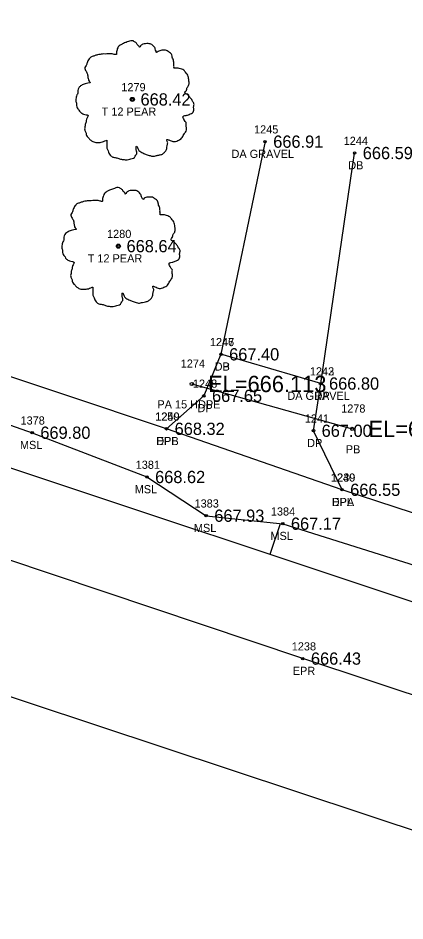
# Model space of a CAD drawing. Extents: x 1655137 to 1657928, y 1003994 to 1005407.
# Drawn here: x 1656148.5 to 1656195.9, y 1004645.1 to 1004755.9 of the extents above; entities that cross this region are included whole.
import ezdxf

# ---------------------------------------------------------------- set-up
doc = ezdxf.new("R2010")
doc.units = 0
for name, color, linetype in [('RD_EX_DR_Pipe', 7, 'Continuous'), ('RD_EX_DR_Pipe_txCode', 7, 'Continuous'), ('RD_EX_Driveway', 7, 'Continuous'), ('RD_EX_Driveway_txCode', 7, 'Continuous'), ('RD_EX_Fence_Other', 7, 'Continuous'), ('RD_EX_Misc', 7, 'Continuous'), ('RD_EX_Misc_txCode', 7, 'Continuous'), ('RD_EX_Road', 7, 'Continuous'), ('RD_EX_Road_txCode', 7, 'Continuous'), ('RD_EX_TX_Driveway_ELEV', 7, 'Continuous'), ('RD_EX_TX_Misc_ELEV', 7, 'Continuous'), ('RD_EX_TX_Road_ELEV', 7, 'Continuous'), ('RD_EX_TX_VEG_ELEV', 7, 'Continuous'), ('RD_EX_VEG', 7, 'Continuous'), ('RD_EX_VEG_txCode', 7, 'Continuous'), ('RD_HC_Cl', 7, 'Continuous'), ('RD_HC_Data_Tic', 7, 'Continuous'), ('RD_SMD_Locator', 7, 'Continuous'), ('RD_TX_Pipe_ElevEX', 7, 'Continuous')]:
    doc.layers.add(name, color=color, linetype=linetype)

msp = doc.modelspace()

# ---------------------------------------------------------------- linework, layer by layer
at = {"layer": 'RD_EX_DR_Pipe'}
msp.add_line((1656169.82, 1004711.01), (1656189.47, 1004705.5), dxfattribs=at)
at = {"layer": 'RD_EX_Driveway'}
for p, q in [((1656178.8, 1004740.74), (1656173.4, 1004714.65)), ((1656185.64, 1004711.06), (1656189.77, 1004739.34))]:
    msp.add_line(p, q, dxfattribs=at)
msp.add_lwpolyline([(1656188.23, 1004698.03), (1656184.73, 1004705.27), (1656185.64, 1004711.06), (1656173.4, 1004714.65), (1656171.3, 1004709.55), (1656166.72, 1004705.51)], dxfattribs=at)
at = {"layer": 'RD_EX_Fence_Other'}
msp.add_lwpolyline([(1656052.39, 1004677.71), (1656061.84, 1004701.05), (1656117.12, 1004682.78), (1656207.41, 1004652.79), (1656216.44, 1004637.08), (1656207.49, 1004611.28)], dxfattribs=at)
at = {"layer": 'RD_EX_Misc'}
msp.add_lwpolyline([(1655875.57, 1004783.81), (1655899.12, 1004775.73), (1655924.14, 1004767.92), (1655957.49, 1004756.44), (1655982.24, 1004748.48), (1656011.78, 1004739.5), (1656033.16, 1004732.17), (1656057.84, 1004724.63), (1656091.05, 1004714.31), (1656106.3, 1004710.84), (1656119.06, 1004707.85), (1656127.53, 1004711.03), (1656137.41, 1004709.54), (1656150.27, 1004705.03), (1656164.33, 1004699.6), (1656171.58, 1004694.85), (1656180.97, 1004693.87), (1656197.98, 1004688.49), (1656215.11, 1004682.58), (1656240.68, 1004675.39), (1656271.88, 1004665.01), (1656304.44, 1004655.08)], dxfattribs=at)
at = {"layer": 'RD_EX_Road'}
for points in [[(1656365.12, 1004639.99), (1656336.04, 1004649.34), (1656302.55, 1004660.37), (1656279.15, 1004668.23), (1656240.07, 1004681.05), (1656188.23, 1004698.03), (1656166.72, 1004705.51), (1656141.16, 1004714.06), (1656093.11, 1004730.11), (1656044.16, 1004746.75), (1655996.36, 1004762.45), (1655947.2, 1004778.68), (1655899.09, 1004794.03), (1655850.62, 1004809.99), (1655801.91, 1004826.1), (1655753.09, 1004842.31), (1655704.25, 1004858.1)], [(1656358.5, 1004619.83), (1656328.78, 1004629.48), (1656280.77, 1004645.39), (1656247.66, 1004656.11), (1656244.5, 1004656.52), (1656222.03, 1004663.57), (1656217.65, 1004665.96), (1656183.42, 1004677.32), (1656134.59, 1004693.72), (1656086.19, 1004709.75), (1656037.58, 1004726.13), (1655989.57, 1004741.99), (1655940.62, 1004757.88), (1655892.37, 1004773.61), (1655843.48, 1004789.36), (1655805.73, 1004801.4), (1655779.22, 1004810.43), (1655768.8, 1004813.1), (1655744.59, 1004822.13), (1655698.83, 1004837.65)]]:
    msp.add_lwpolyline(points, dxfattribs=at)
at = {"layer": 'RD_EX_VEG'}
msp.add_lwpolyline([(1656061.84, 1004701.05), (1656117.12, 1004682.78), (1656207.41, 1004652.79)], dxfattribs=at)
for centre, radius in [((1656162.54, 1004745.92), 0.25), ((1656162.53, 1004745.91), 0.0001), ((1656160.83, 1004727.92), 0.25), ((1656160.82, 1004727.9), 0.0001)]:
    msp.add_circle(centre, radius, dxfattribs=at)
for points in [[(1656162.67, 1004753.09), (1656162.37, 1004753.12), (1656162.05, 1004753.02), (1656161.8, 1004752.92), (1656161.57, 1004752.84), (1656161.35, 1004752.74), (1656161.05, 1004752.57), (1656160.82, 1004752.37), (1656160.7, 1004752.12), (1656160.65, 1004751.89), (1656160.6, 1004751.62), (1656160.6, 1004751.44), (1656160.47, 1004751.42), (1656160.32, 1004751.44), (1656160.07, 1004751.52), (1656159.82, 1004751.52), (1656159.57, 1004751.52), (1656159.22, 1004751.49), (1656158.87, 1004751.49), (1656158.6, 1004751.44), (1656158.27, 1004751.39), (1656157.9, 1004751.27), (1656157.55, 1004751.14), (1656157.25, 1004750.89), (1656157, 1004750.42), (1656156.87, 1004750.07), (1656156.72, 1004749.82), (1656156.87, 1004749.37), (1656157.05, 1004749.02), (1656157.07, 1004748.82), (1656157.15, 1004748.39), (1656157.25, 1004748.17), (1656157.37, 1004747.97), (1656157.3, 1004747.94), (1656156.92, 1004747.89), (1656156.62, 1004747.79), (1656156.2, 1004747.57), (1656155.97, 1004747.34), (1656155.87, 1004747.02), (1656155.85, 1004746.67), (1656155.75, 1004746.47), (1656155.67, 1004746.19), (1656155.65, 1004746.12), (1656155.6, 1004745.79), (1656155.7, 1004745.34), (1656155.72, 1004745), (1656155.85, 1004744.77), (1656156, 1004744.6), (1656156.17, 1004744.35), (1656156.57, 1004744.12), (1656156.9, 1004744.02), (1656157.1, 1004744), (1656156.92, 1004743.5), (1656156.87, 1004743.15), (1656156.75, 1004742.75), (1656156.75, 1004742.67), (1656156.7, 1004742.2), (1656156.85, 1004741.87), (1656156.92, 1004741.5), (1656157.1, 1004741.27), (1656157.37, 1004740.97), (1656157.7, 1004740.75), (1656158.2, 1004740.62), (1656158.6, 1004740.65), (1656159.17, 1004740.82), (1656159.42, 1004740.9), (1656159.4, 1004740.72), (1656159.42, 1004740.35), (1656159.42, 1004739.92), (1656159.57, 1004739.6), (1656159.67, 1004739.32), (1656159.82, 1004739.07), (1656160.15, 1004738.85), (1656160.55, 1004738.77), (1656160.97, 1004738.62), (1656161.42, 1004738.55), (1656161.92, 1004738.52), (1656162.52, 1004738.67), (1656162.8, 1004738.8), (1656162.9, 1004738.97), (1656163.1, 1004739.35), (1656163.05, 1004739.57), (1656163.07, 1004740.17), (1656163.17, 1004740), (1656163.35, 1004739.65), (1656163.84, 1004739.35), (1656164.24, 1004739.17), (1656164.72, 1004739.02), (1656165.02, 1004738.95), (1656165.49, 1004739.02), (1656165.87, 1004739.1), (1656166.24, 1004739.22), (1656166.54, 1004739.5), (1656166.72, 1004739.77), (1656166.77, 1004740.05), (1656166.84, 1004740.42), (1656166.89, 1004740.6)], [(1656166.89, 1004740.6), (1656166.82, 1004740.77), (1656166.77, 1004741.02), (1656166.84, 1004741), (1656167.02, 1004740.95), (1656167.29, 1004740.82), (1656167.52, 1004740.75), (1656167.84, 1004740.77), (1656168.12, 1004740.87), (1656168.57, 1004741.15), (1656168.84, 1004741.62), (1656169.12, 1004742.02), (1656169.19, 1004742.35), (1656169.14, 1004742.57), (1656169.12, 1004743.07), (1656168.92, 1004743.32), (1656168.87, 1004743.45), (1656168.77, 1004743.85), (1656168.84, 1004743.9), (1656169.12, 1004743.95), (1656169.49, 1004744.07), (1656169.77, 1004744.2), (1656169.99, 1004744.37), (1656170.07, 1004744.6), (1656170.04, 1004745), (1656170.09, 1004745.39), (1656170.02, 1004745.54), (1656169.92, 1004745.69), (1656169.84, 1004745.89), (1656169.69, 1004746.04), (1656169.59, 1004746.19), (1656169.49, 1004746.29), (1656169.37, 1004746.44), (1656169.19, 1004746.57), (1656169.04, 1004746.62), (1656168.99, 1004746.77), (1656169.14, 1004746.97), (1656169.19, 1004747.07), (1656169.22, 1004747.29), (1656169.44, 1004747.64), (1656169.49, 1004748.04), (1656169.44, 1004748.47), (1656169.39, 1004748.74), (1656169.24, 1004749.02), (1656169.04, 1004749.27), (1656168.92, 1004749.44), (1656168.74, 1004749.57), (1656168.42, 1004749.69), (1656168.17, 1004749.74), (1656167.82, 1004749.74), (1656167.62, 1004749.79), (1656167.64, 1004749.84), (1656167.64, 1004749.99), (1656167.64, 1004750.27), (1656167.57, 1004750.72), (1656167.42, 1004751.22), (1656167.42, 1004751.24), (1656167.32, 1004751.49), (1656167.09, 1004751.69), (1656166.92, 1004751.79), (1656166.72, 1004751.92), (1656166.47, 1004751.94), (1656166.17, 1004751.94), (1656165.89, 1004751.89), (1656165.69, 1004751.79), (1656165.52, 1004751.67), (1656165.44, 1004751.82), (1656165.34, 1004752.12), (1656165.29, 1004752.27), (1656165.14, 1004752.44), (1656164.92, 1004752.64), (1656164.47, 1004752.77), (1656163.84, 1004752.69), (1656163.55, 1004752.49), (1656163.4, 1004752.32), (1656163.35, 1004752.44), (1656163.15, 1004752.64), (1656163.05, 1004752.82), (1656162.87, 1004752.94), (1656162.72, 1004753.04), (1656162.62, 1004753.09)], [(1656160.96, 1004735.09), (1656160.66, 1004735.11), (1656160.34, 1004735.01), (1656160.09, 1004734.91), (1656159.86, 1004734.84), (1656159.64, 1004734.74), (1656159.34, 1004734.56), (1656159.11, 1004734.36), (1656158.99, 1004734.11), (1656158.94, 1004733.89), (1656158.89, 1004733.61), (1656158.89, 1004733.44), (1656158.76, 1004733.41), (1656158.61, 1004733.44), (1656158.36, 1004733.51), (1656158.11, 1004733.51), (1656157.86, 1004733.51), (1656157.51, 1004733.49), (1656157.16, 1004733.49), (1656156.89, 1004733.44), (1656156.56, 1004733.39), (1656156.19, 1004733.26), (1656155.84, 1004733.14), (1656155.54, 1004732.89), (1656155.29, 1004732.41), (1656155.16, 1004732.06), (1656155.01, 1004731.81), (1656155.16, 1004731.36), (1656155.34, 1004731.01), (1656155.36, 1004730.81), (1656155.44, 1004730.39), (1656155.54, 1004730.16), (1656155.66, 1004729.96), (1656155.59, 1004729.94), (1656155.21, 1004729.89), (1656154.91, 1004729.79), (1656154.49, 1004729.56), (1656154.26, 1004729.34), (1656154.16, 1004729.01), (1656154.14, 1004728.66), (1656154.04, 1004728.46), (1656153.96, 1004728.19), (1656153.94, 1004728.11), (1656153.89, 1004727.79), (1656153.99, 1004727.34), (1656154.01, 1004726.99), (1656154.14, 1004726.77), (1656154.29, 1004726.59), (1656154.46, 1004726.34), (1656154.86, 1004726.12), (1656155.19, 1004726.02), (1656155.39, 1004725.99), (1656155.21, 1004725.49), (1656155.16, 1004725.14), (1656155.04, 1004724.74), (1656155.04, 1004724.67), (1656154.99, 1004724.19), (1656155.14, 1004723.87), (1656155.21, 1004723.49), (1656155.39, 1004723.27), (1656155.66, 1004722.97), (1656155.99, 1004722.74), (1656156.49, 1004722.62), (1656156.89, 1004722.64), (1656157.46, 1004722.82), (1656157.71, 1004722.89), (1656157.69, 1004722.72), (1656157.71, 1004722.34), (1656157.71, 1004721.92), (1656157.86, 1004721.59), (1656157.96, 1004721.32), (1656158.11, 1004721.07), (1656158.44, 1004720.84), (1656158.84, 1004720.77), (1656159.26, 1004720.62), (1656159.71, 1004720.54), (1656160.21, 1004720.52), (1656160.81, 1004720.67), (1656161.08, 1004720.79), (1656161.18, 1004720.97), (1656161.38, 1004721.34), (1656161.33, 1004721.57), (1656161.36, 1004722.17), (1656161.46, 1004721.99), (1656161.63, 1004721.64), (1656162.13, 1004721.34), (1656162.53, 1004721.17), (1656163.01, 1004721.02), (1656163.31, 1004720.94), (1656163.78, 1004721.02), (1656164.16, 1004721.09), (1656164.53, 1004721.22), (1656164.83, 1004721.49), (1656165.01, 1004721.77), (1656165.06, 1004722.04), (1656165.13, 1004722.42), (1656165.18, 1004722.59)], [(1656165.18, 1004722.59), (1656165.11, 1004722.77), (1656165.06, 1004723.02), (1656165.13, 1004722.99), (1656165.31, 1004722.94), (1656165.58, 1004722.82), (1656165.81, 1004722.74), (1656166.13, 1004722.77), (1656166.41, 1004722.87), (1656166.86, 1004723.14), (1656167.13, 1004723.62), (1656167.41, 1004724.02), (1656167.48, 1004724.34), (1656167.43, 1004724.57), (1656167.41, 1004725.07), (1656167.21, 1004725.32), (1656167.16, 1004725.44), (1656167.06, 1004725.84), (1656167.13, 1004725.89), (1656167.41, 1004725.94), (1656167.78, 1004726.07), (1656168.06, 1004726.19), (1656168.28, 1004726.37), (1656168.36, 1004726.59), (1656168.33, 1004726.99), (1656168.38, 1004727.39), (1656168.31, 1004727.54), (1656168.21, 1004727.69), (1656168.13, 1004727.89), (1656167.98, 1004728.04), (1656167.88, 1004728.19), (1656167.78, 1004728.29), (1656167.66, 1004728.44), (1656167.48, 1004728.56), (1656167.33, 1004728.61), (1656167.28, 1004728.76), (1656167.43, 1004728.96), (1656167.48, 1004729.06), (1656167.51, 1004729.29), (1656167.73, 1004729.64), (1656167.78, 1004730.04), (1656167.73, 1004730.46), (1656167.68, 1004730.74), (1656167.53, 1004731.01), (1656167.33, 1004731.26), (1656167.21, 1004731.44), (1656167.03, 1004731.56), (1656166.71, 1004731.69), (1656166.46, 1004731.74), (1656166.11, 1004731.74), (1656165.91, 1004731.79), (1656165.93, 1004731.84), (1656165.93, 1004731.99), (1656165.93, 1004732.26), (1656165.86, 1004732.71), (1656165.71, 1004733.21), (1656165.71, 1004733.24), (1656165.61, 1004733.49), (1656165.38, 1004733.69), (1656165.21, 1004733.79), (1656165.01, 1004733.91), (1656164.76, 1004733.94), (1656164.46, 1004733.94), (1656164.18, 1004733.89), (1656163.98, 1004733.79), (1656163.81, 1004733.66), (1656163.73, 1004733.81), (1656163.63, 1004734.11), (1656163.58, 1004734.26), (1656163.43, 1004734.44), (1656163.21, 1004734.64), (1656162.76, 1004734.76), (1656162.13, 1004734.69), (1656161.83, 1004734.49), (1656161.68, 1004734.31), (1656161.63, 1004734.44), (1656161.43, 1004734.64), (1656161.33, 1004734.81), (1656161.16, 1004734.94), (1656161.01, 1004735.04), (1656160.91, 1004735.09)]]:
    msp.add_spline(points, degree=3, dxfattribs=at)
at = {"layer": 'RD_HC_Cl'}
msp.add_line((1656069.26, 1004726.84), (1656507.36, 1004580.77), dxfattribs=at)
at = {"layer": 'RD_HC_Data_Tic'}
msp.add_line((1656179.44, 1004690.11), (1656180.7, 1004693.9), dxfattribs=at)
at = {"layer": 'RD_SMD_Locator'}
for centre, radius in [((1656162.54, 1004745.92), 0.15), ((1656178.8, 1004740.74), 0.15), ((1656189.77, 1004739.34), 0.15), ((1656160.83, 1004727.92), 0.15), ((1656173.4, 1004714.65), 0.15), ((1656173.4, 1004714.65), 0.15), ((1656169.82, 1004711.01), 0.2), ((1656185.64, 1004711.06), 0.15), ((1656185.64, 1004711.06), 0.15), ((1656171.3, 1004709.55), 0.15), ((1656150.27, 1004705.03), 0.15), ((1656166.72, 1004705.51), 0.15), ((1656166.72, 1004705.51), 0.15), ((1656184.73, 1004705.27), 0.15), ((1656189.47, 1004705.5), 0.2), ((1656164.33, 1004699.6), 0.15), ((1656188.23, 1004698.03), 0.15), ((1656188.23, 1004698.03), 0.15), ((1656171.58, 1004694.85), 0.15), ((1656180.97, 1004693.87), 0.15), ((1656183.42, 1004677.32), 0.15)]:
    msp.add_circle(centre, radius, dxfattribs=at)

# ---------------------------------------------------------------- texts
at = {"layer": 'RD_EX_DR_Pipe_txCode'}
for s, p in [('1274', (1656168.47, 1004713.01)), ('PA 15 HDPE', (1656165.61, 1004708.01)), ('1278', (1656188.12, 1004707.5)), ('PB', (1656188.69, 1004702.5))]:
    msp.add_text(s, height=1, dxfattribs=at).set_placement(p)
at = {"layer": 'RD_EX_Driveway_txCode'}
for s, p in [('1245', (1656177.45, 1004741.74)), ('1244', (1656188.43, 1004740.34)), ('DA GRAVEL', (1656174.69, 1004738.74)), ('DB', (1656188.99, 1004737.34)), ('1246', (1656172.03, 1004715.65)), ('1247', (1656172.05, 1004715.65)), ('DB', (1656172.62, 1004712.65)), ('DP', (1656172.62, 1004712.65)), ('1242', (1656184.29, 1004712.06)), ('1243', (1656184.29, 1004712.06)), ('1248', (1656169.96, 1004710.55)), ('DA GRAVEL', (1656181.53, 1004709.06)), ('DP', (1656184.86, 1004709.06)), ('DP', (1656170.52, 1004707.55)), ('1249', (1656165.37, 1004706.51)), ('1241', (1656183.67, 1004706.27)), ('DPB', (1656165.47, 1004703.51)), ('DP', (1656183.95, 1004703.27)), ('1240', (1656186.85, 1004699.03)), ('DPA', (1656186.97, 1004696.03))]:
    msp.add_text(s, height=1, dxfattribs=at).set_placement(p)
at = {"layer": 'RD_EX_Misc_txCode'}
for s, p in [('1378', (1656148.84, 1004706.03)), ('MSL', (1656148.77, 1004703.03)), ('1381', (1656162.95, 1004700.6)), ('MSL', (1656162.83, 1004697.6)), ('1383', (1656170.16, 1004695.85)), ('1384', (1656179.51, 1004694.87)), ('MSL', (1656170.08, 1004692.85)), ('MSL', (1656179.46, 1004691.87))]:
    msp.add_text(s, height=1, dxfattribs=at).set_placement(p)
at = {"layer": 'RD_EX_Road_txCode'}
for s, p in [('1250', (1656165.33, 1004706.51)), ('EPL', (1656165.51, 1004703.51)), ('1239', (1656186.89, 1004699.03)), ('EPL', (1656187.03, 1004696.03)), ('1238', (1656182.07, 1004678.32)), ('EPR', (1656182.19, 1004675.32))]:
    msp.add_text(s, height=1, dxfattribs=at).set_placement(p)
at = {"layer": 'RD_EX_TX_Driveway_ELEV'}
for s, p in [('666.91', (1656179.8, 1004739.99)), ('666.59', (1656190.77, 1004738.59)), ('667.40', (1656174.4, 1004713.9)), ('667.40', (1656174.4, 1004713.9)), ('666.80', (1656186.64, 1004710.31)), ('666.80', (1656186.64, 1004710.31)), ('667.65', (1656172.3, 1004708.8)), ('668.32', (1656167.72, 1004704.76)), ('667.00', (1656185.73, 1004704.52)), ('666.55', (1656189.23, 1004697.28))]:
    msp.add_text(s, height=1.5, dxfattribs=at).set_placement(p)
at = {"layer": 'RD_EX_TX_Misc_ELEV'}
for s, p in [('669.80', (1656151.27, 1004704.28)), ('668.62', (1656165.33, 1004698.85)), ('667.93', (1656172.58, 1004694.1)), ('667.17', (1656181.97, 1004693.12))]:
    msp.add_text(s, height=1.5, dxfattribs=at).set_placement(p)
at = {"layer": 'RD_EX_TX_Road_ELEV'}
for s, p in [('668.32', (1656167.72, 1004704.76)), ('666.55', (1656189.23, 1004697.28)), ('666.43', (1656184.42, 1004676.57))]:
    msp.add_text(s, height=1.5, dxfattribs=at).set_placement(p)
at = {"layer": 'RD_EX_TX_VEG_ELEV'}
for s, p in [('668.42', (1656163.54, 1004745.17)), ('668.64', (1656161.83, 1004727.17))]:
    msp.add_text(s, height=1.5, dxfattribs=at).set_placement(p)
at = {"layer": 'RD_EX_VEG_txCode'}
for s, p in [('1279', (1656161.19, 1004746.92)), ('T 12 PEAR', (1656158.78, 1004743.92)), ('1280', (1656159.44, 1004728.92)), ('T 12 PEAR', (1656157.07, 1004725.92))]:
    msp.add_text(s, height=1, dxfattribs=at).set_placement(p)
at = {"layer": 'RD_TX_Pipe_ElevEX'}
for s, p in [('EL=666.113', (1656171.82, 1004710.01)), ('EL=664.205', (1656191.47, 1004704.5))]:
    msp.add_text(s, height=2, dxfattribs=at).set_placement(p)

doc.saveas('drawing.dxf')
